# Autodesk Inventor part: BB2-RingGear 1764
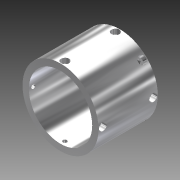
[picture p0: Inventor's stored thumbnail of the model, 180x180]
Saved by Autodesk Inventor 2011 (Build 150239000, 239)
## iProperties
Company: FirstCadLibrary
Shininess: 64.0
Length Units: 11269
Angle Units: 11279
Time Units: 11290
Mass Units: 11283
Length Display Precision: 3
Angle Display Precision: 2
Compacted: True
Part Number: BB2-RingGear 1764
Document SubType Name: Modeling
Created: 2007-01
Designer: Ed Sparks
Material: Steel, Mild
Catalog Web Link: www.banebots.com
Vendor: BaneBots
Mass: 305.335 g
Surface Area: 187.703 cm^2
Volume: 38.8467 cm^3
Density: 7.86 g/cm^3
Density: 0.0
Volumn: 0.0
Area: 0.0
PropertySet Name: Model Information
Control State: 0
Master: False
Checked Out: False
Author: Ed Sparks
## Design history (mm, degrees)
sketch "Sketch1"
  geometry: C1 r 25 at (0, 0); C2 r 30 at (0, 0); 1 further point
  constraints: 2 centre point, 2 coincident, 1 concentric, 1 other
  dimensions: "d0" = 50 diameter of C1; "d1" = 60 diameter of C2
extrude "Extrusion1" new body sketch "Sketch1" distance "d2" = 46.8; taper "d3" = 0 deg
workplane "Work Plane1"
sketch "Sketch3"
  geometry: L1 (-30, 0)-(30, 0) reference; L2 (0, 0)-(0, 28.195); 1 further point
  constraints: 2 end point, 1 midpoint, 1 perpendicular, 1 point on line
  dimensions: "d5" = 3.5 distance from line of L1 point (0, 3.5)
hole "Hole1" sketch "Sketch3" at (0, 3.5) diameter "d6" = 3.2; stored, may be unused: countersink angle "d10" = 82 deg, drill point angle "d12" = 118 deg; dims "d7" = 6, "d8" = 6.2, "d9" = 4.2, "d11" = 8
pattern_circular "Circular Pattern1" dims angle "d15" = 360 deg
sketch "Sketch4"
  geometry: L1 (-30, 46.8)-(30, 46.8) reference; L2 (0, 46.8)-(0, 26.14); 1 further point
  constraints: 2 end point, 1 midpoint, 1 perpendicular, 1 point on line
  dimensions: "d16" = 3.5 distance from line of L1 point (0, 43.3)
hole "Hole2" sketch "Sketch4" at (0, 43.3) diameter "d17" = 3.2; stored, may be unused: countersink angle "d21" = 82 deg, drill point angle "d23" = 118 deg; dims "d18" = 6, "d19" = 6.2, "d20" = 4.2, "d22" = 8
pattern_circular "Circular Pattern2" dims angle "d26" = 360 deg
body "Solid1"
